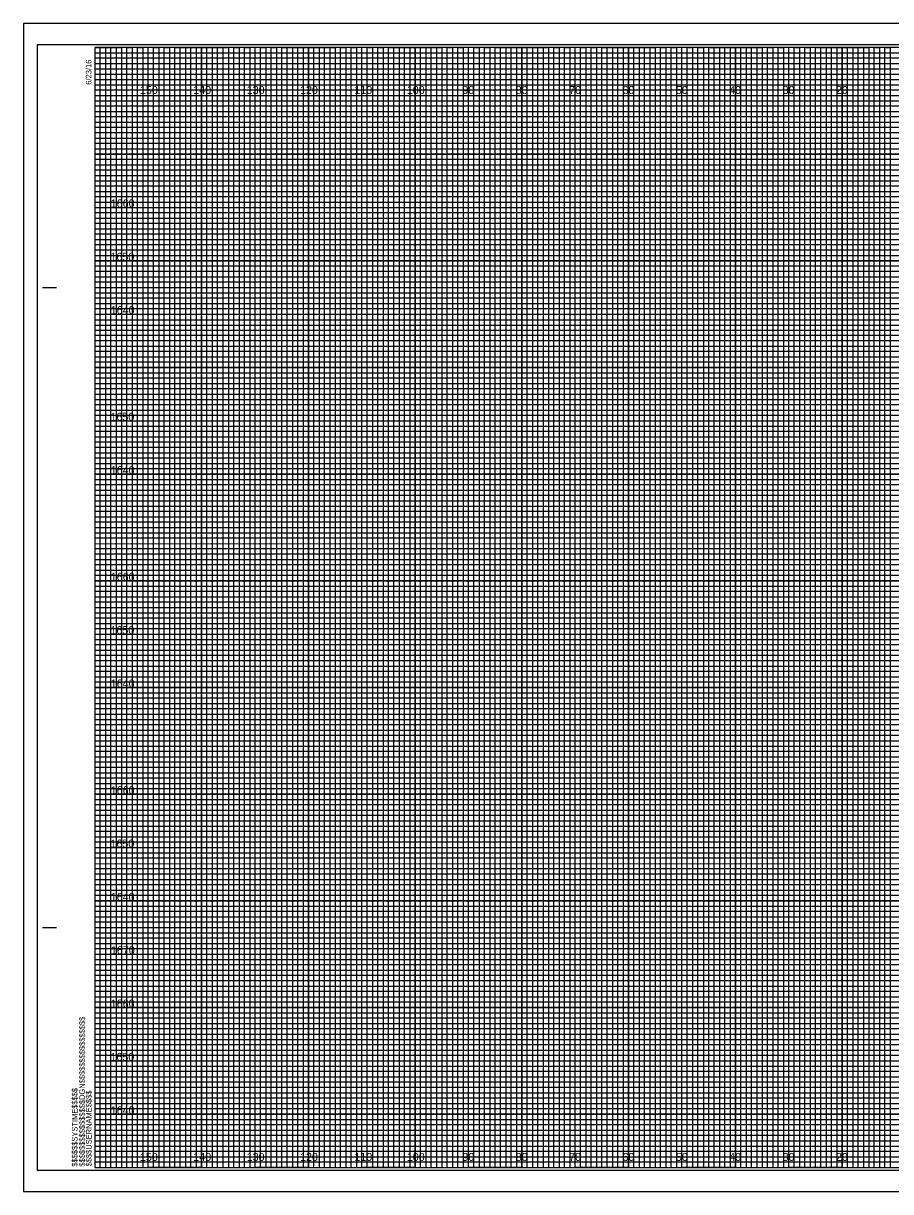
# Model space of a CAD drawing. Extents: x -423 to -87, y -23 to 1516.
# Drawn here: x -423.3 to -260.8, y -22.7 to 196.3 of the extents above; entities that cross this region are included whole.
import ezdxf

# ---------------------------------------------------------------- set-up
doc = ezdxf.new("R2010")
doc.units = 0
for name, color, linetype in [('Prop Horizontal Alignment', 7, 'Continuous'), ('Prop XS DDE', 7, 'Continuous'), ('Prop XS DDE Elevations', 7, 'Continuous'), ('Prop XS DDE Slope Text', 7, 'Continuous'), ('Prop XS Earthwork Shape', 7, 'Continuous'), ('Scratch_Level_3', 7, 'Continuous'), ('Sheet Cross Section Grid Minor 2 CELL', 7, 'Continuous'), ('Sheet Cutting Line CELL', 7, 'Continuous'), ('Sheet DOT Grid CELL', 7, 'Continuous'), ('Sheet Plot Border Inside CELL', 7, 'Continuous'), ('Sheet Plot Border Outside CELL', 7, 'Continuous')]:
    doc.layers.add(name, color=color, linetype=linetype)

msp = doc.modelspace()

# ---------------------------------------------------------------- linework, layer by layer
at = {"layer": 'Prop XS DDE'}
for points in [[(-409.86, 191.8), (-404.86, 191.8), (-404.86, -18.2), (-394.86, -18.2), (-394.86, 191.8), (-384.86, 191.8), (-384.86, -18.2), (-374.86, -18.2), (-374.86, 191.8), (-364.86, 191.8), (-364.86, -18.2), (-354.86, -18.2), (-354.86, 191.8), (-344.86, 191.8), (-344.86, -18.2), (-334.86, -18.2), (-334.86, 191.8), (-324.86, 191.8), (-324.86, -18.2), (-314.86, -18.2), (-314.86, 191.8), (-304.86, 191.8), (-304.86, -18.2), (-294.86, -18.2), (-294.86, 191.8), (-284.86, 191.8), (-284.86, -18.2), (-274.86, -18.2), (-274.86, 191.8), (-264.86, 191.8), (-264.86, -18.2), (-254.86, -18.2)], [(-409.86, 186.8), (-134.86, 186.8)], [(-409.86, 166.8), (-89.86, 166.8), (-89.86, 176.8), (-409.86, 176.8)], [(-409.86, 146.8), (-89.86, 146.8), (-89.86, 156.8), (-409.86, 156.8)], [(-409.86, 126.8), (-89.86, 126.8), (-89.86, 136.8), (-409.86, 136.8)], [(-409.86, 106.8), (-89.86, 106.8), (-89.86, 116.8), (-409.86, 116.8)], [(-409.86, 86.8), (-89.86, 86.8), (-89.86, 96.8), (-409.86, 96.8)], [(-409.86, 66.8), (-89.86, 66.8), (-89.86, 76.8), (-409.86, 76.8)], [(-409.86, 46.8), (-89.86, 46.8), (-89.86, 56.8), (-409.86, 56.8)], [(-409.86, 26.8), (-89.86, 26.8), (-89.86, 36.8), (-409.86, 36.8)], [(-409.86, 6.8), (-89.86, 6.8), (-89.86, 16.8), (-409.86, 16.8)], [(-409.86, -13.2), (-89.86, -13.2), (-89.86, -3.2), (-409.86, -3.2)]]:
    msp.add_lwpolyline(points, dxfattribs=at)
at = {"layer": 'Prop XS DDE Elevations'}
for p, q in [((-419.66, 146.8), (-417.16, 146.8)), ((-419.56, 146.8), (-417.06, 146.8)), ((-419.66, 26.8), (-417.16, 26.8)), ((-419.56, 26.8), (-417.06, 26.8)), ((-409.86, -18.2), (-409.86, -18.2)), ((-409.86, -18.2), (-409.86, -18.2)), ((-409.86, -18.2), (-409.86, -18.2)), ((-409.86, -18.2), (-409.86, -18.2)), ((-409.86, -18.2), (-409.86, -18.2)), ((-409.86, -18.2), (-409.86, -18.2)), ((-409.86, -18.2), (-409.86, -18.2))]:
    msp.add_line(p, q, dxfattribs=at)
msp.add_lwpolyline([(-89.86, 191.8), (-409.86, 191.8), (-409.86, -18.2), (-89.86, -18.2)], close=True, dxfattribs=at)
at = {"layer": 'Prop XS DDE Slope Text'}
for p, q in [((-409.86, 190.8), (-149.86, 190.8)), ((-149.86, 189.78), (-409.86, 189.78)), ((-409.86, 189.78), (-409.86, 188.8)), ((-409.86, 188.8), (-149.86, 188.8)), ((-149.86, 187.69), (-409.86, 187.69)), ((-409.86, 187.69), (-409.86, 185.8)), ((-409.86, 185.8), (-89.86, 185.8))]:
    msp.add_line(p, q, dxfattribs=at)
for points in [[(-409.86, 184.8), (-139.86, 184.8), (-89.86, 184.8), (-89.86, 183.8), (-409.86, 183.8)], [(-409.86, 182.8), (-89.86, 182.8), (-89.86, 180.8), (-409.86, 180.8)], [(-409.86, 179.8), (-89.86, 179.8), (-89.86, 178.8), (-409.86, 178.78)], [(-409.86, 177.8), (-89.86, 177.8), (-89.86, 175.8), (-409.86, 175.8)], [(-409.86, 174.8), (-89.86, 174.8), (-89.86, 173.8), (-409.86, 173.8)], [(-409.86, 172.8), (-89.86, 172.8), (-89.86, 170.8), (-409.86, 170.8)], [(-409.86, 169.8), (-89.86, 169.8), (-89.86, 168.8), (-409.86, 168.8)], [(-409.86, 167.8), (-89.86, 167.8), (-89.86, 165.8), (-409.86, 165.8)], [(-409.86, 164.8), (-89.86, 164.8), (-89.86, 163.8), (-409.86, 163.8)], [(-409.86, 162.8), (-89.86, 162.8), (-89.86, 160.8), (-409.86, 160.8)], [(-409.86, 159.8), (-89.86, 159.8), (-89.86, 158.8), (-409.86, 158.8)], [(-409.86, 157.8), (-89.86, 157.8), (-89.86, 155.75), (-89.86, 154.8), (-89.86, 153.8), (-409.86, 153.8)], [(-409.86, 155.8), (-89.86, 155.8), (-89.86, 154.8), (-409.86, 154.8)], [(-409.86, 152.8), (-89.86, 152.8), (-89.86, 150.8), (-409.86, 150.83)], [(-409.86, 150.83), (-89.86, 150.8), (-89.86, 149.8), (-409.86, 149.8)], [(-409.86, 148.8), (-89.86, 148.8), (-89.86, 147.8), (-409.86, 147.8)], [(-409.86, 145.8), (-89.86, 145.8), (-89.86, 144.8), (-409.86, 144.8)], [(-409.86, 143.8), (-89.86, 143.8), (-89.86, 142.8), (-409.86, 142.8)], [(-409.93, 140.69), (-89.86, 140.69), (-89.86, 139.68), (-409.93, 139.68)], [(-409.86, 138.8), (-89.86, 138.8), (-89.86, 137.8), (-409.86, 137.8)], [(-409.86, 135.8), (-89.86, 135.8), (-89.86, 134.8), (-409.86, 134.8)], [(-409.86, 133.8), (-89.86, 133.8), (-89.86, 132.8), (-409.86, 132.8)], [(-409.86, 130.8), (-89.86, 130.8), (-89.86, 129.8), (-409.86, 129.8)], [(-409.86, 128.8), (-89.86, 128.8), (-89.86, 127.8), (-409.86, 127.8)], [(-409.86, 125.8), (-89.86, 125.8), (-89.86, 124.8), (-409.86, 124.8)], [(-409.86, 123.8), (-89.86, 123.8), (-89.86, 122.8), (-409.86, 122.8)], [(-409.86, 120.8), (-89.86, 120.8), (-89.87, 119.78), (-409.86, 119.8)], [(-409.86, 118.8), (-89.86, 118.8), (-89.86, 117.8), (-409.86, 117.8)], [(-409.86, 115.8), (-89.86, 115.8), (-89.86, 114.8), (-409.86, 114.8)], [(-409.86, 113.8), (-89.86, 113.8), (-89.86, 112.8), (-409.86, 112.8)], [(-409.86, 110.8), (-89.86, 110.8), (-89.86, 109.8), (-409.86, 109.8)], [(-409.86, 108.8), (-89.86, 108.8), (-89.86, 107.8), (-409.86, 107.8)], [(-409.86, 105.8), (-89.86, 105.8), (-89.86, 104.8), (-409.86, 104.8)], [(-409.86, 103.8), (-89.86, 103.8), (-89.86, 102.8), (-409.86, 102.8)], [(-409.86, 100.8), (-89.86, 100.8), (-89.86, 99.8), (-409.86, 99.8)], [(-409.86, 98.79), (-89.79, 98.71), (-89.86, 97.8), (-409.86, 97.8)], [(-409.86, 95.8), (-89.86, 95.8), (-89.86, 94.8), (-409.86, 94.8)], [(-409.86, 93.8), (-89.86, 93.8), (-89.86, 92.8), (-409.86, 92.8)], [(-409.86, 90.8), (-89.86, 90.8), (-89.86, 89.8), (-409.86, 89.8)], [(-409.86, 88.8), (-89.86, 88.8), (-89.86, 87.8), (-409.86, 87.8)], [(-409.86, 85.8), (-89.86, 85.8), (-89.86, 84.8), (-409.86, 84.8)], [(-409.86, 83.8), (-89.86, 83.8), (-89.86, 82.8), (-409.86, 82.8)], [(-409.86, 80.8), (-89.86, 80.8), (-89.86, 79.8), (-409.86, 79.8)], [(-409.86, 78.8), (-89.86, 78.8), (-89.86, 77.8), (-409.86, 77.8)], [(-409.86, 75.8), (-89.86, 75.8), (-89.86, 74.8), (-409.86, 74.8)], [(-409.86, 73.8), (-89.86, 73.8), (-89.86, 72.8), (-409.86, 72.8)], [(-409.86, 70.8), (-89.86, 70.8), (-89.86, 69.8), (-409.86, 69.8)], [(-409.86, 68.8), (-89.86, 68.8), (-89.86, 67.8), (-409.86, 67.8)], [(-409.86, 65.8), (-89.86, 65.8), (-89.86, 64.8), (-409.86, 64.8)], [(-409.86, 63.8), (-89.86, 63.8), (-89.86, 62.8), (-409.86, 62.8)], [(-409.86, 60.8), (-89.86, 60.8), (-89.87, 59.78), (-409.86, 59.8)], [(-409.86, 58.8), (-89.86, 58.8), (-89.86, 57.8), (-409.86, 57.8)], [(-409.86, 55.8), (-89.86, 55.8), (-89.86, 54.8), (-409.86, 54.8)], [(-409.86, 53.8), (-89.86, 53.8), (-89.86, 52.8), (-409.86, 52.8)], [(-409.86, 50.8), (-89.86, 50.8), (-89.86, 49.8), (-409.86, 49.8)], [(-409.86, 48.8), (-89.86, 48.8), (-89.86, 47.8), (-409.86, 47.8)], [(-409.86, 45.8), (-89.86, 45.8), (-89.86, 44.8), (-409.86, 44.8)], [(-409.86, 43.8), (-89.86, 43.8), (-89.86, 42.8), (-409.86, 42.8)], [(-409.86, 40.8), (-89.86, 40.8), (-89.86, 39.8), (-409.86, 39.8)], [(-409.86, 38.79), (-89.79, 38.71), (-89.86, 37.8), (-409.86, 37.8)], [(-409.86, 35.8), (-89.86, 35.8), (-89.86, 34.8), (-409.86, 34.8)], [(-409.86, 33.8), (-89.86, 33.8), (-89.86, 32.8), (-409.86, 32.8)], [(-409.86, 30.8), (-89.86, 30.8), (-89.86, 29.8), (-409.86, 29.8)], [(-409.86, 28.8), (-89.86, 28.8), (-89.86, 27.8), (-409.86, 27.8)], [(-409.86, 25.8), (-89.86, 25.8), (-89.86, 24.8), (-409.86, 24.8)], [(-409.86, 23.8), (-89.86, 23.8), (-89.86, 22.8), (-409.86, 22.8)], [(-409.86, 20.8), (-89.86, 20.8), (-89.86, 19.8), (-409.86, 19.8)], [(-409.86, 18.8), (-89.86, 18.8), (-89.86, 17.8), (-409.86, 17.8)], [(-409.86, 15.8), (-89.86, 15.8), (-89.86, 14.8), (-409.86, 14.8)], [(-409.86, 13.8), (-89.86, 13.8), (-89.86, 12.8), (-409.86, 12.8)], [(-409.86, 10.8), (-89.86, 10.8), (-89.86, 9.8), (-409.86, 9.8)], [(-409.86, 8.8), (-89.86, 8.8), (-89.86, 7.8), (-409.86, 7.8)], [(-409.86, 5.8), (-89.86, 5.8), (-89.86, 4.8), (-409.86, 4.8)], [(-409.86, 3.8), (-89.86, 3.8), (-89.86, 2.8), (-409.86, 2.8)], [(-409.86, 0.8), (-89.86, 0.8), (-89.86, -0.2), (-409.86, -0.2)], [(-409.86, -1.2), (-89.86, -1.2), (-89.86, -2.2), (-409.86, -2.2)], [(-409.86, -4.2), (-89.86, -4.2), (-89.86, -5.2), (-409.86, -5.2)], [(-409.86, -6.2), (-89.86, -6.2), (-89.86, -7.2), (-409.86, -7.2)], [(-409.86, -9.2), (-89.86, -9.2), (-89.86, -10.2), (-409.86, -10.2)], [(-409.86, -11.2), (-89.86, -11.2), (-89.86, -12.2), (-409.86, -12.2)], [(-409.86, -14.2), (-89.86, -14.2), (-89.86, -15.2), (-409.86, -15.2)], [(-409.86, -16.2), (-89.86, -16.2), (-89.86, -17.2), (-409.86, -17.2)]]:
    msp.add_lwpolyline(points, dxfattribs=at)
at = {"layer": 'Prop XS Earthwork Shape'}
for p, q in [((-399.86, 191.8), (-409.86, 191.8)), ((-399.86, -18.2), (-399.86, 191.8)), ((-379.86, 191.8), (-389.86, 191.8)), ((-389.86, 191.8), (-389.86, -18.2)), ((-379.86, -18.2), (-379.86, 191.8)), ((-359.86, 191.8), (-369.86, 191.8)), ((-369.86, 191.8), (-369.86, -18.2)), ((-359.86, -18.2), (-359.86, 191.8)), ((-339.86, 191.8), (-349.86, 191.8)), ((-349.86, 191.8), (-349.86, -18.2)), ((-339.86, -18.2), (-339.86, 191.8)), ((-319.86, 191.8), (-329.86, 191.8)), ((-329.86, 191.8), (-329.86, -18.2)), ((-319.86, -18.2), (-319.86, 191.8)), ((-299.86, 191.8), (-309.86, 191.8)), ((-309.86, 191.8), (-309.86, -18.2)), ((-299.86, -18.2), (-299.86, 191.8)), ((-279.86, 191.8), (-289.86, 191.8)), ((-289.86, 191.8), (-289.86, -18.2)), ((-279.86, -18.2), (-279.86, 191.8)), ((-259.86, 191.8), (-269.86, 191.8)), ((-269.86, 191.8), (-269.86, -18.2)), ((-389.86, -18.2), (-399.86, -18.2)), ((-369.86, -18.2), (-379.86, -18.2)), ((-349.86, -18.2), (-359.86, -18.2)), ((-329.86, -18.2), (-339.86, -18.2)), ((-309.86, -18.2), (-319.86, -18.2)), ((-289.86, -18.2), (-299.86, -18.2)), ((-269.86, -18.2), (-279.86, -18.2))]:
    msp.add_line(p, q, dxfattribs=at)
for points in [[(-409.86, 181.8), (-89.86, 181.8), (-89.86, 171.8), (-409.86, 171.8)], [(-409.86, 161.8), (-89.86, 161.8), (-89.86, 151.8), (-409.86, 151.8)], [(-409.86, 141.8), (-89.86, 141.8), (-89.86, 131.8), (-409.86, 131.8)], [(-409.86, 121.8), (-89.86, 121.8), (-89.86, 111.8), (-409.86, 111.8)], [(-409.86, 101.8), (-89.86, 101.8), (-89.86, 91.8), (-409.86, 91.8)], [(-409.86, 81.8), (-89.86, 81.8), (-89.86, 71.8), (-409.86, 71.8)], [(-409.86, 61.8), (-89.86, 61.8), (-89.86, 51.8), (-409.86, 51.8)], [(-409.86, 41.8), (-89.86, 41.8), (-89.86, 31.8), (-409.86, 31.8)], [(-409.86, 21.8), (-89.86, 21.8), (-89.86, 11.8), (-409.86, 11.8)], [(-409.86, 1.8), (-89.86, 1.8), (-89.86, -8.2), (-409.86, -8.2)]]:
    msp.add_lwpolyline(points, dxfattribs=at)
at = {"layer": 'Sheet Cross Section Grid Minor 2 CELL'}
for points in [[(-409.86, -18.2), (-408.86, -18.2), (-408.86, 191.8), (-407.86, 191.8), (-407.86, -18.2)], [(-407.86, -18.2), (-406.86, -18.2), (-406.86, 191.8), (-405.86, 191.8), (-405.86, -18.2)], [(-404.86, -18.2), (-403.86, -18.2), (-403.86, 191.8), (-402.86, 191.8), (-402.86, -18.2)], [(-402.86, -18.2), (-401.86, -18.2), (-401.86, 191.8), (-400.86, 191.8), (-400.86, -18.2)], [(-399.86, -18.2), (-398.86, -18.2), (-398.86, 191.8), (-397.86, 191.8), (-397.86, -18.2)], [(-397.86, -18.2), (-396.86, -18.2), (-396.86, 191.8), (-395.86, 191.8), (-395.86, -18.2)], [(-394.86, -18.2), (-393.86, -18.2), (-393.86, 191.8), (-392.86, 191.8), (-392.86, -18.2)], [(-392.86, -18.2), (-391.86, -18.2), (-391.86, 191.8), (-390.86, 191.8), (-390.86, -18.2)], [(-389.86, -18.2), (-388.86, -18.2), (-388.86, 191.8), (-387.86, 191.8), (-387.86, -18.2)], [(-387.86, -18.2), (-386.86, -18.2), (-386.86, 191.8), (-385.86, 191.8), (-385.86, -18.2)], [(-384.86, -18.2), (-383.86, -18.2), (-383.86, 191.8), (-382.86, 191.8), (-382.86, -18.2)], [(-382.86, -18.2), (-381.86, -18.2), (-381.86, 191.8), (-380.86, 191.8), (-380.86, -18.2)], [(-379.86, -18.2), (-378.86, -18.2), (-378.86, 191.8), (-377.86, 191.8), (-377.86, -18.2)], [(-377.86, -18.2), (-376.86, -18.2), (-376.86, 191.8), (-375.86, 191.8), (-375.86, -18.2)], [(-374.86, -18.2), (-373.86, -18.2), (-373.86, 191.8), (-372.86, 191.8), (-372.86, -18.2)], [(-372.86, -18.2), (-371.86, -18.2), (-371.86, 191.8), (-370.86, 191.8), (-370.86, -18.2)], [(-369.86, -18.2), (-368.86, -18.2), (-368.86, 191.8), (-367.86, 191.8), (-367.86, -18.2)], [(-367.86, -18.2), (-366.86, -18.2), (-366.86, 191.8), (-365.86, 191.8), (-365.86, -18.2)], [(-364.86, -18.2), (-363.86, -18.2), (-363.86, 191.8), (-362.86, 191.8), (-362.86, -18.2)], [(-362.86, -18.2), (-361.86, -18.2), (-361.86, 191.8), (-360.86, 191.8), (-360.86, -18.2)], [(-359.86, -18.2), (-358.86, -18.2), (-358.86, 191.8), (-357.86, 191.8), (-357.86, -18.2)], [(-357.86, -18.2), (-356.86, -18.2), (-356.86, 191.8), (-355.86, 191.8), (-355.86, -18.2)], [(-354.86, -18.2), (-353.86, -18.2), (-353.86, 191.8), (-352.86, 191.8), (-352.86, -18.2)], [(-352.86, -18.2), (-351.86, -18.2), (-351.86, 191.8), (-350.86, 191.8), (-350.86, -18.2)], [(-349.86, -18.2), (-348.86, -18.2), (-348.86, 191.8), (-347.86, 191.8), (-347.86, -18.2)], [(-347.86, -18.2), (-346.86, -18.2), (-346.86, 191.8), (-345.86, 191.8), (-345.86, -18.2)], [(-344.86, -18.2), (-343.86, -18.2), (-343.86, 191.8), (-342.86, 191.8), (-342.86, -18.2)], [(-342.86, -18.2), (-341.86, -18.2), (-341.86, 191.8), (-340.86, 191.8), (-340.86, -18.2)], [(-339.86, -18.2), (-338.86, -18.2), (-338.86, 191.8), (-337.86, 191.8), (-337.86, -18.2)], [(-337.86, -18.2), (-336.86, -18.2), (-336.86, 191.8), (-335.86, 191.8), (-335.86, -18.2)], [(-334.86, -18.2), (-333.86, -18.2), (-333.86, 191.8), (-332.86, 191.8), (-332.86, -18.2)], [(-332.86, -18.2), (-331.86, -18.2), (-331.86, 191.8), (-330.86, 191.8), (-330.86, -18.2)], [(-329.86, -18.2), (-328.86, -18.2), (-328.86, 191.8), (-327.86, 191.8), (-327.86, -18.2)], [(-327.86, -18.2), (-326.86, -18.2), (-326.86, 191.8), (-325.86, 191.8), (-325.86, -18.2)], [(-324.86, -18.2), (-323.86, -18.2), (-323.86, 191.8), (-322.86, 191.8), (-322.86, -18.2)], [(-322.86, -18.2), (-321.86, -18.2), (-321.86, 191.8), (-320.86, 191.8), (-320.86, -18.2)], [(-319.86, -18.2), (-318.86, -18.2), (-318.86, 191.8), (-317.86, 191.8), (-317.86, -18.2)], [(-317.86, -18.2), (-316.86, -18.2), (-316.86, 191.8), (-315.86, 191.8), (-315.86, -18.2)], [(-314.86, -18.2), (-313.86, -18.2), (-313.86, 191.8), (-312.86, 191.8), (-312.86, -18.2)], [(-312.86, -18.2), (-311.86, -18.2), (-311.86, 191.8), (-310.86, 191.8), (-310.86, -18.2)], [(-309.86, -18.2), (-308.86, -18.2), (-308.86, 191.8), (-307.86, 191.8), (-307.86, -18.2)], [(-307.86, -18.2), (-306.86, -18.2), (-306.86, 191.8), (-305.86, 191.8), (-305.86, -18.2)], [(-304.86, -18.2), (-303.86, -18.2), (-303.86, 191.8), (-302.86, 191.8), (-302.86, -18.2)], [(-302.86, -18.2), (-301.86, -18.2), (-301.86, 191.8), (-300.86, 191.8), (-300.86, -18.2)], [(-299.86, -18.2), (-298.86, -18.2), (-298.86, 191.8), (-297.86, 191.8), (-297.86, -18.2)], [(-297.86, -18.2), (-296.86, -18.2), (-296.86, 191.8), (-295.86, 191.8), (-295.86, -18.2)], [(-294.86, -18.2), (-293.86, -18.2), (-293.86, 191.8), (-292.86, 191.8), (-292.86, -18.2)], [(-292.86, -18.2), (-291.86, -18.2), (-291.86, 191.8), (-290.86, 191.8), (-290.86, -18.2)], [(-289.86, -18.2), (-288.86, -18.2), (-288.86, 191.8), (-287.86, 191.8), (-287.86, -18.2)], [(-287.86, -18.2), (-286.86, -18.2), (-286.86, 191.8), (-285.86, 191.8), (-285.86, -18.2)], [(-284.86, -18.2), (-283.86, -18.2), (-283.86, 191.8), (-282.86, 191.8), (-282.86, -18.2)], [(-282.86, -18.2), (-281.86, -18.2), (-281.86, 191.8), (-280.86, 191.8), (-280.86, -18.2)], [(-279.86, -18.2), (-278.86, -18.2), (-278.86, 191.8), (-277.86, 191.8), (-277.86, -18.2)], [(-277.86, -18.2), (-276.86, -18.2), (-276.86, 191.8), (-275.86, 191.8), (-275.86, -18.2)], [(-274.86, -18.2), (-273.86, -18.2), (-273.86, 191.8), (-272.86, 191.8), (-272.86, -18.2)], [(-272.86, -18.2), (-271.86, -18.2), (-271.86, 191.8), (-270.86, 191.8), (-270.86, -18.2)], [(-269.86, -18.2), (-268.86, -18.2), (-268.86, 191.8), (-267.86, 191.8), (-267.86, -18.2)], [(-267.86, -18.2), (-266.86, -18.2), (-266.86, 191.8), (-265.86, 191.8), (-265.86, -18.2)], [(-264.86, -18.2), (-263.86, -18.2), (-263.86, 191.8), (-262.86, 191.8), (-262.86, -18.2)], [(-262.86, -18.2), (-261.86, -18.2), (-261.86, 191.8), (-260.86, 191.8), (-260.86, -18.2)]]:
    msp.add_lwpolyline(points, dxfattribs=at)
at = {"layer": 'Sheet Cutting Line CELL'}
for p, q in [((-86.56, 196.3), (-423.26, 196.3)), ((-423.26, 196.3), (-423.26, -22.7)), ((-423.26, -22.7), (-86.56, -22.7))]:
    msp.add_line(p, q, dxfattribs=at)
at = {"layer": 'Sheet DOT Grid CELL'}
for p, q in [((-399.86, -18.2), (-399.86, 191.8)), ((-389.86, -18.2), (-389.86, 191.8)), ((-379.86, -18.2), (-379.86, 191.8)), ((-369.86, -18.2), (-369.86, 191.8)), ((-359.86, -18.2), (-359.86, 191.8)), ((-349.86, -18.2), (-349.86, 191.8)), ((-339.86, -18.2), (-339.86, 191.8)), ((-329.86, -18.2), (-329.86, 191.8)), ((-319.86, -18.2), (-319.86, 191.8)), ((-309.86, -18.2), (-309.86, 191.8)), ((-299.86, -18.2), (-299.86, 191.8)), ((-289.86, -18.2), (-289.86, 191.8)), ((-279.86, -18.2), (-279.86, 191.8)), ((-269.86, -18.2), (-269.86, 191.8)), ((-409.86, 181.8), (-89.86, 181.8)), ((-409.86, 171.8), (-89.86, 171.8)), ((-409.86, 161.8), (-89.86, 161.8)), ((-409.86, 151.8), (-89.86, 151.8)), ((-409.86, 141.8), (-89.86, 141.8)), ((-409.86, 131.8), (-89.86, 131.8)), ((-409.86, 121.8), (-89.86, 121.8)), ((-409.86, 111.8), (-89.86, 111.8)), ((-409.86, 101.8), (-89.86, 101.8)), ((-409.86, 91.8), (-89.86, 91.8)), ((-409.86, 81.8), (-89.86, 81.8)), ((-409.86, 71.8), (-89.86, 71.8)), ((-409.86, 61.8), (-89.86, 61.8)), ((-409.86, 51.8), (-89.86, 51.8)), ((-409.86, 41.8), (-89.86, 41.8)), ((-409.86, 31.8), (-89.86, 31.8)), ((-409.86, 21.8), (-89.86, 21.8)), ((-409.86, 11.8), (-89.86, 11.8)), ((-409.86, 1.8), (-89.86, 1.8)), ((-409.86, -8.2), (-89.86, -8.2))]:
    msp.add_line(p, q, dxfattribs=at)
at = {"layer": 'Sheet Plot Border Inside CELL'}
msp.add_lwpolyline([(-420.66, -18.7), (-87.46, -18.7), (-87.46, 192.3), (-420.66, 192.3)], close=True, dxfattribs=at)
at = {"layer": 'Sheet Plot Border Outside CELL'}
msp.add_lwpolyline([(-423.26, -22.7), (-86.56, -22.7), (-86.56, 196.3), (-423.26, 196.3)], close=True, dxfattribs=at)

# ---------------------------------------------------------------- texts
at = {"layer": 'Prop Horizontal Alignment'}
for s, p in [('1660', (-406.89, 161.8)), ('1650', (-406.94, 151.8)), ('1640', (-406.89, 141.8)), ('1650', (-406.94, 121.8)), ('1640', (-406.89, 111.8)), ('1660', (-406.89, 91.8)), ('1650', (-406.94, 81.8)), ('1640', (-406.89, 71.8)), ('1660', (-406.89, 51.8)), ('1650', (-406.94, 41.8)), ('1640', (-406.89, 31.8)), ('1670', (-406.86, 21.8)), ('1660', (-406.89, 11.8)), ('1650', (-406.94, 1.8)), ('1640', (-406.89, -8.2))]:
    msp.add_text(s, height=1.5, dxfattribs=at).set_placement(p)
at = {"layer": 'Prop XS DDE Elevations'}
for s, p in [('6/23/16', (-410.51, 184.8)), ('$$$$$$$$$$$$$$$$DGN$$$$$$$$$$$$$$$$', (-411.74, -18.02)), ('$$$$$$SYSTIME$$$$$', (-413.12, -18.02)), ('$$$$USERNAME$$$$', (-410.48, -17.97))]:
    msp.add_text(s, height=1.05, rotation=90, dxfattribs=at).set_placement(p)
at = {"layer": 'Scratch_Level_3'}
for s, p in [('150', (-401.42, 183.05)), ('140', (-391.42, 183.05)), ('130', (-381.42, 183.05)), ('120', (-371.42, 183.05)), ('110', (-361.24, 183.05)), ('100', (-351.42, 183.05)), ('90', (-341.01, 183.05)), ('80', (-331.01, 183.05)), ('70', (-321.01, 183.05)), ('60', (-311.01, 183.05)), ('50', (-301.01, 183.05)), ('40', (-291.01, 183.05)), ('30', (-281.01, 183.05)), ('20', (-271.01, 183.05)), ('150', (-401.42, -16.95)), ('140', (-391.42, -16.95)), ('130', (-381.42, -16.95)), ('120', (-371.42, -16.95)), ('110', (-361.24, -16.95)), ('100', (-351.42, -16.95)), ('90', (-341.01, -16.95)), ('80', (-331.01, -16.95)), ('70', (-321.01, -16.95)), ('60', (-311.01, -16.95)), ('50', (-301.01, -16.95)), ('40', (-291.01, -16.95)), ('30', (-281.01, -16.95)), ('20', (-271.01, -16.95))]:
    msp.add_text(s, height=1.5, dxfattribs=at).set_placement(p)

doc.saveas('drawing.dxf')
